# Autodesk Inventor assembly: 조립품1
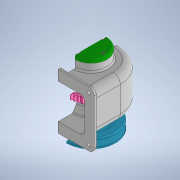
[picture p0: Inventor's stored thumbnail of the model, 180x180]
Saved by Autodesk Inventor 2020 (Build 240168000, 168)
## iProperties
Created: 2022-09
Part Number: 조립품1
Document SubType Name: Assembly
Designer: Administrator
Author: Administrator
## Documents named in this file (16)
- C:\Users\Administrator\Desktop\720906V1012\조립품1.iam
- C:\Users\Administrator\Desktop\720906V1012\본체.ipt
- C:\Users\Administrator\Desktop\720906V1012\축.ipt
- C:\Users\Administrator\Desktop\720906V1012\키 6 x 6 x 22.ipt
- C:\Users\Administrator\Desktop\720906V1012\스퍼기어.ipt
- C:\Users\Administrator\Desktop\720906V1012\칼라.ipt
- C:\Users\Administrator\Desktop\720906V1012\베어링 6203.ipt
- C:\Users\Administrator\Desktop\720906V1012\앞커버.ipt
- C:\Users\Administrator\Desktop\720906V1012\뒤커버.ipt
- C:\Users\Administrator\Desktop\720906V1012\오일 실 17 x 30 x 8.ipt
- C:\Users\Administrator\Desktop\720906V1012\볼트 M3 x 10.ipt
- C:\Users\Administrator\Desktop\720906V1012\키 5 x 5 x 18.ipt
- C:\Users\Administrator\Desktop\720906V1012\V-벨트풀리.ipt
- C:\Users\Administrator\Desktop\720906V1012\멈춤나사 M4 x 10.ipt
- C:\Users\Administrator\Desktop\720906V1012\와셔 6 x 22.ipt
- C:\Users\Administrator\Desktop\720906V1012\육각머리볼트 M3 x 8.ipt
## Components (9 placed, 2 different names)
1. V-벨트풀리:1 — 각도:2
2. ISO 4762 M3 x 10:1
3. ISO 4762 M3 x 10:2
4. ISO 4762 M3 x 10:3
5. ISO 4762 M3 x 10:4
6. ISO 4762 M3 x 10:5
7. ISO 4762 M3 x 10:6
8. ISO 4762 M3 x 10:7
9. ISO 4762 M3 x 10:8
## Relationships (1: Angle 1)
- 각도:2 [Angle]: V-벨트풀리:1
